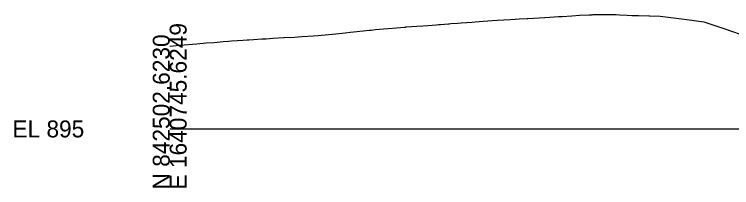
# Model space of a CAD drawing. Extents: x -26 to 1640245, y -10 to 842531.
# Drawn here: x -25.7 to 92.9, y 1490.3 to 1518.9 of the extents above; entities that cross this region are included whole.
import ezdxf

# ---------------------------------------------------------------- set-up
doc = ezdxf.new("R2010")
doc.units = 0
for name, color, linetype in [('Default', 7, 'Continuous'), ('Exist Cross Section Cell', 7, 'Continuous'), ('Exist XS Ground Line', 7, 'Continuous')]:
    doc.layers.add(name, color=color, linetype=linetype)

msp = doc.modelspace()

# ---------------------------------------------------------------- linework, layer by layer
at = {"layer": 'Exist Cross Section Cell'}
msp.add_line((0, 1500), (150, 1500), dxfattribs=at)
at = {"layer": 'Exist XS Ground Line'}
for p, q in [((62.04, 1518.41), (62.85, 1518.47)), ((62.85, 1518.47), (64.29, 1518.55)), ((64.29, 1518.55), (64.69, 1518.57)), ((64.69, 1518.57), (64.91, 1518.58)), ((64.91, 1518.58), (66.52, 1518.68)), ((66.52, 1518.68), (67.79, 1518.76)), ((67.79, 1518.76), (69.39, 1518.84)), ((69.39, 1518.84), (69.86, 1518.86)), ((69.86, 1518.86), (70.03, 1518.87)), ((70.03, 1518.87), (70.67, 1518.9)), ((70.67, 1518.9), (72.46, 1518.91)), ((72.46, 1518.91), (73.55, 1518.91)), ((73.55, 1518.91), (73.85, 1518.89)), ((73.85, 1518.89), (74.37, 1518.86)), ((74.37, 1518.86), (75.68, 1518.78)), ((75.68, 1518.78), (76.43, 1518.72)), ((76.43, 1518.72), (77.51, 1518.71)), ((77.51, 1518.71), (79.31, 1518.68)), ((79.31, 1518.68), (79.38, 1518.67)), ((79.38, 1518.67), (81.12, 1518.64)), ((81.12, 1518.64), (85.52, 1518.05)), ((44.12, 1517.21), (44.53, 1517.24)), ((44.53, 1517.24), (44.76, 1517.26)), ((44.76, 1517.26), (46.13, 1517.37)), ((46.13, 1517.37), (46.19, 1517.37)), ((46.19, 1517.37), (46.51, 1517.4)), ((46.51, 1517.4), (47.64, 1517.48)), ((47.64, 1517.48), (48.19, 1517.52)), ((48.19, 1517.52), (49.16, 1517.59)), ((49.16, 1517.59), (50.03, 1517.65)), ((50.03, 1517.65), (50.52, 1517.68)), ((50.52, 1517.68), (51.86, 1517.78)), ((51.86, 1517.78), (53.4, 1517.88)), ((53.4, 1517.88), (54.2, 1517.93)), ((54.2, 1517.93), (56.28, 1518.06)), ((56.28, 1518.06), (57.15, 1518.12)), ((57.15, 1518.12), (57.81, 1518.17)), ((57.81, 1518.17), (59.14, 1518.25)), ((59.14, 1518.25), (59.16, 1518.25)), ((59.16, 1518.25), (59.19, 1518.25)), ((59.19, 1518.25), (59.24, 1518.25)), ((59.24, 1518.25), (62.04, 1518.41)), ((85.52, 1518.05), (88.31, 1517.68)), ((88.31, 1517.68), (91.63, 1516.56)), ((30.37, 1516.01), (31.97, 1516.18)), ((31.97, 1516.18), (33.01, 1516.3)), ((33.01, 1516.3), (33.29, 1516.33)), ((33.29, 1516.33), (34.03, 1516.41)), ((34.03, 1516.41), (35.37, 1516.53)), ((35.37, 1516.53), (36.13, 1516.59)), ((36.13, 1516.59), (38.91, 1516.82)), ((38.91, 1516.82), (39.01, 1516.82)), ((39.01, 1516.82), (39.03, 1516.83)), ((39.03, 1516.83), (39.08, 1516.83)), ((39.08, 1516.83), (40.86, 1516.96)), ((40.86, 1516.96), (41.88, 1517.03)), ((41.88, 1517.03), (42.7, 1517.1)), ((42.7, 1517.1), (44.12, 1517.21)), ((91.63, 1516.56), (97.98, 1514.41)), ((15.21, 1514.85), (15.98, 1514.89)), ((15.98, 1514.89), (17.04, 1514.96)), ((17.04, 1514.96), (18.85, 1515.07)), ((18.85, 1515.07), (18.91, 1515.07)), ((18.91, 1515.07), (20.71, 1515.16)), ((20.71, 1515.16), (21.24, 1515.21)), ((21.24, 1515.21), (21.91, 1515.25)), ((21.91, 1515.25), (23.73, 1515.36)), ((23.73, 1515.36), (24.57, 1515.41)), ((24.57, 1515.41), (25.08, 1515.46)), ((25.08, 1515.46), (27.49, 1515.69)), ((27.49, 1515.69), (28.99, 1515.86)), ((28.99, 1515.86), (29.87, 1515.95)), ((29.87, 1515.95), (30.37, 1516.01)), ((0, 1513.68), (0.03, 1513.68)), ((0.03, 1513.68), (0.07, 1513.68)), ((0.07, 1513.68), (1.58, 1513.81)), ((1.58, 1513.81), (2.38, 1513.88)), ((2.38, 1513.88), (3.78, 1514)), ((3.78, 1514), (4.46, 1514.06)), ((4.46, 1514.06), (6.05, 1514.19)), ((6.05, 1514.19), (7.34, 1514.29)), ((7.34, 1514.29), (8.82, 1514.41)), ((8.82, 1514.41), (9.71, 1514.48)), ((9.71, 1514.48), (10.22, 1514.52)), ((10.22, 1514.52), (12.12, 1514.66)), ((12.12, 1514.66), (12.8, 1514.7)), ((12.8, 1514.7), (13.08, 1514.73)), ((13.08, 1514.73), (13.87, 1514.77)), ((13.87, 1514.77), (15.21, 1514.85))]:
    msp.add_line(p, q, dxfattribs=at)

# ---------------------------------------------------------------- texts
at = {"layer": 'Default'}
msp.add_text('-', height=0.0001, dxfattribs=at).set_placement((0, 1500))
at = {"layer": 'Exist Cross Section Cell'}
for s, p in [('E 1640745.6249', (2.8, 1490)), ('N 842502.6230', (0, 1490))]:
    msp.add_text(s, height=2.8, rotation=90, dxfattribs=at).set_placement(p)
msp.add_text('EL 895', height=2.8, dxfattribs=at).set_placement((-26, 1498.6))

doc.saveas('drawing.dxf')
